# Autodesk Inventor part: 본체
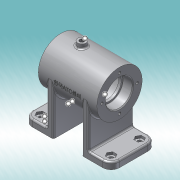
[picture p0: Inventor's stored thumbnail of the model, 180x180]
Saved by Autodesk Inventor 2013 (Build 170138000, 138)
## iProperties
Created: 2017-02
Part Number: 본체
Material: 알루미늄 6061
Document SubType Name: Modeling
Designer: dgall
Density: 1 g/cm^3
Author: dgall
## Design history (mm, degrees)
sketch "스케치1"
  geometry: C1 r 27 at (0, 0); 1 further point
  constraints: 1 centre point, 1 coincident
  dimensions: "d15" = 54 diameter of C1
extrude "돌출1" new body sketch "스케치1" stored distance "d17" = 70; taper "d18" = 0 deg
hole "구멍1" diameter "d21" = 28; stored, may be unused: countersink angle "d25" = 90 deg, drill point angle "d27" = 0 deg; dims "d19" = 10, "d20" = 10, "d22" = 6, "d23" = 32, "d24" = 12, "d26" = 15
sketch "스케치2"
  geometry: C1 r 14 at (0, 0) reference; C2 r 22 at (0, 0)
  constraints: 1 centre point, 1 coincident
  dimensions: "d28" = 44 diameter of C2
extrude "돌출2" cut sketch "스케치2" distance "d30" = 40; taper "d31" = 0 deg
chamfer "모따기1" distance "d32" = 1; stored, may be unused: second distance "d33" = 2, angle "d34" = 45 deg
fillet "모깎기1" dims "d35" = 0.3
fillet "모깎기2" dims "d36" = 2
sketch "스케치3" dims "d37" = 42
  geometry: C1 r 27 at (0, 0) reference; C2 r 17 at (0, 0) reference; 2 further points
  constraints: 2 vertical alignment, 1 coincident, 2 other
hole "구멍2" sketch "스케치3" at (0, 21) diameter "d39" = 3.242; stored, may be unused: countersink angle "d43" = 90 deg, drill point angle "d45" = 118 deg; dims "d40" = 8, "d41" = 32, "d42" = 12, "d44" = 10
node "작업 평면1"
sketch "스케치4"
  geometry: L1 (27, 35)-(-27, 35) reference; C1 r 5 at (0, 10); 1 further point
  constraints: 1 centre point, 1 vertical alignment
  dimensions: "d49" = 10 diameter of C1; "d51" = 25 distance from line of C1.centre L1
extrude "돌출3" join sketch "스케치4" stored distance "d53" = 40; taper "d54" = 0 deg
hole "구멍3" diameter "d57" = 5.188; stored, may be unused: countersink angle "d61" = 90 deg, drill point angle "d63" = 0 deg; dims "d55" = 10, "d56" = 10, "d58" = 8, "d59" = 32, "d60" = 12, "d62" = 10
node "작업 평면2"
sketch "스케치5"
  geometry: L1 (-27, 52)-(27, 52); L2 (27, -52)-(-27, -52); L3 (-27, 0)-(27, 0); L4 (-27, 17)-(27, 17); L5 (-27, 25)-(27, 25); L6 (-27, -17)-(27, -17); L7 (-27, -25)-(27, -25); L8 (-27, -52)-(-27, -17); L9 (-27, 17)-(-27, 52); L10 (27, 52)-(27, 17); L11 (27, -17)-(27, -52); 2 further points
  constraints: 22 end point, 14 perpendicular, 4 point on line, 1 horizontal, 1 horizontal alignment, 1 midpoint, 1 vertical alignment
  dimensions: "d66" = 54 distance of L1.start L1.end; "d67" = 104 distance of L1.end L2.start; "d68" = 54 distance of L2.start L2.end; "d70" = 17 distance between parallel lines of L3 L4; "d71" = 8 distance between parallel lines of L4 L5; "d72" = 17 distance between parallel lines of L6 L3; "d73" = 8 distance between parallel lines of L7 L6; "d74" = 35 distance of L2.end L6.start; "d75" = 35 distance of L4.start L1.start; "d76" = 104 distance between parallel lines of L2 L1; "d77" = 52 distance between parallel lines of L3 L1
extrude "돌출4" join sketch "스케치5" stored distance "d78" = 40; taper "d79" = 0 deg
extrude "돌출5" join sketch "스케치5" distance "d80" = 8; taper "d81" = 0 deg
fillet "모깎기3" dims "d82" = 10
sketch "스케치6" dims "d84" = 9, "d86" = 9
  geometry: L1 (-12.5, -44.598)-(-17, -47.196); L2 (-17, -47.196)-(-21.5, -44.598); L3 (-21.5, -44.598)-(-21.5, -39.402); L4 (-21.5, -39.402)-(-17, -36.804); L5 (-17, -36.804)-(-12.5, -39.402); L6 (-12.5, -39.402)-(-12.5, -44.598); L7 (21.5, -44.598)-(17, -47.196); L8 (17, -47.196)-(12.5, -44.598); L9 (12.5, -44.598)-(12.5, -39.402); L10 (12.5, -39.402)-(17, -36.804); L11 (17, -36.804)-(21.5, -39.402); L12 (21.5, -39.402)-(21.5, -44.598); A1 r 10 centre (-17, -42) between (-27, -42) and (-17, -52) reference; A2 r 10 centre (17, -42) between (17, -52) and (27, -42) reference; 7 further points
  constraints: 24 end point, 4 coincident, 2 horizontal alignment, 2 midpoint, 30 other
  dimensions: "d87" = 4.5 horizontal distance of L1.start L1.end; "d88" = 4.5 horizontal distance of L7.start L7.end
extrude "돌출6" cut sketch "스케치6" distance "d89" = 3; taper "d90" = 0 deg
hole "구멍4" diameter "d93" = 5; stored, may be unused: countersink angle "d97" = 90 deg, drill point angle "d99" = 0 deg; dims "d91" = 10, "d92" = 10, "d94" = 8, "d95" = 32, "d96" = 12, "d98" = 10
hole "구멍5" diameter "d104" = 5; stored, may be unused: countersink angle "d108" = 90 deg, drill point angle "d110" = 0 deg; dims "d102" = 10, "d103" = 10, "d105" = 8, "d106" = 32, "d107" = 12, "d109" = 10
node "작업 평면3"
sketch "스케치7"
  geometry: L1 (0, 0)-(16.339, -25.16); L2 (0, 0)-(0, -27); A1 r 27 centre (0, 0) between (-27, 0) and (27, 0) reference
  constraints: 4 end point, 1 point on circle
  dimensions: "d114" = 30 distance of L1.start L1.end; "d115" = 33 deg angle of L1 L2
node "작업 평면4"
sketch "스케치8"
  geometry: C1 r 6 at (0, 0); 1 further point
  constraints: 1 centre point, 1 coincident
  dimensions: "d116" = 12 diameter of C1
extrude "돌출7" join sketch "스케치8" stored distance "d118" = 3; taper "d119" = 0 deg
hole "구멍6" diameter "d122" = 5.188; stored, may be unused: countersink angle "d126" = 90 deg, drill point angle "d128" = 0 deg; dims "d120" = 10, "d121" = 10, "d123" = 8, "d124" = 32, "d125" = 12, "d127" = 10
node "작업 평면5"
sketch "스케치9"
  geometry: L1 (27, 35)-(-27, 35) reference; L2 (27, -35)-(27, 35) reference; 2 further points
  constraints: 1 other
  dimensions: "d130" = 35 distance from line of point (0, 0) L1; "d131" = 27 distance from line of L2 point (0, 0)
feature "엠보싱1" sketch "스케치9" dims "d35" = 0.3, "d132" = 0.5, "d133" = 0
fillet "모깎기4" dims "d134" = 2
node "솔리드1"
mirror "대칭1"
pattern_circular "원형 패턴1" dims angle "d47" = 360 deg
mirror "대칭2"
mirror "대칭3"
other parameters: "d52" = 32, "d64" = 0, "d100" = 0, "d101" = 0, "d111" = 0, "d112" = 0, "d113" = -35, "d129" = 0
